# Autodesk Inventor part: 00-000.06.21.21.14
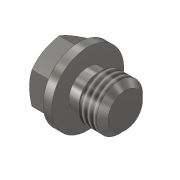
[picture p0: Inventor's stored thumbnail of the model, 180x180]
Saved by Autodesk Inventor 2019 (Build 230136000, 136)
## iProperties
Created: 2019-01
Part Number: 00-000.06.21.21.14
Material: Steel, Mild
Document SubType Name: Modeling
Designer: m.vorobev
Density: 7.85 g/cm^3
Appearance: Semi-Polished
Author: m.vorobev
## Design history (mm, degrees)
sketch "Sketch1"
  geometry: L1 (0, 0)-(-8, 0); L2 (-8, 0)-(-8, 11); L3 (-8, 11)-(0, 11); L4 (0, 11)-(0, 0); L5 (0, 0)-(3, 0); L6 (3, 0)-(3, 12.5); L7 (3, 12.5)-(0, 12.5); L8 (0, 12.5)-(0, 0); L9 (8, 0)-(16, 0); L10 (16, 0)-(16, 8); L11 (16, 8)-(8, 8); L12 (8, 8)-(8, 0); L13 (8, 8)-(6.5, 6.5); L14 (6.5, 6.5)-(3, 6.5); L15 (3, 0)-(8, 0); L16 (-8, 9)-(-6.845, 11); 1 further point
  constraints: 32 end point, 6 parallel, 5 horizontal, 4 point on line, 3 perpendicular, 1 coincident
  dimensions: "d0" = 45 deg angle of L14 L13; "d1" = 25 diameter of L7 L1; "d2" = 24 distance between parallel lines of L10 L2; "d3" = 8 distance of L2.end L3.end; "d4" = 13 distance between parallel lines of L10 L6; "d5" = 16 diameter of L11 L1; "d6" = 5 distance between parallel lines of L12 L6; "d7" = 13 diameter of L14 L1; "d8" = 22 diameter of L3 L1; "d16" = 18 diameter of L16.start L1; "d17" = 30 deg angle of L16 L2
revolve "Revolution1" sketch "Sketch1" stored, may be unused: angle "d9" = 90 deg
chamfer "Chamfer1" distance "d10" = 2; stored, may be unused: second distance "d11" = 2, angle "d12" = 45 deg
sketch "Sketch2"
  geometry: L1 (0, 10.97)-(9.5, 5.485); L2 (9.5, 5.485)-(9.5, -5.485); L3 (9.5, -5.485)-(0, -10.97); L4 (0, -10.97)-(-9.5, -5.485); L5 (-9.5, -5.485)-(-9.5, 5.485); L6 (-9.5, 5.485)-(0, 10.97); C1 r 17.845 at (0, 0); 2 further points
  constraints: 12 end point, 2 coincident, 1 centre point, 1 vertical, 13 other
  dimensions: "d13" = 19 distance between parallel lines of L5 L2
extrude "Extrusion1" cut sketch "Sketch2" stored distance "d14" = 10; taper "d15" = 0 deg
thread "Thread1" dims "d18" = 10, "d19" = 0
body "Solid1"
